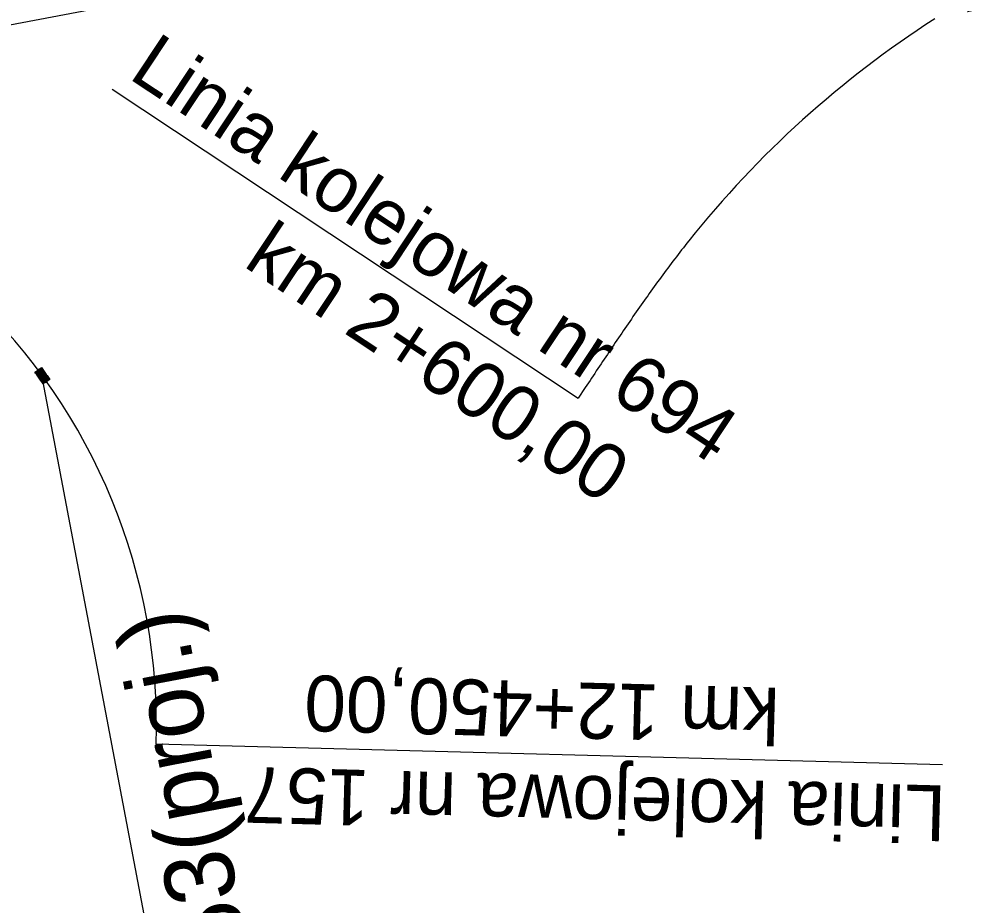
# Model space of a CAD drawing. Extents: x 6540402 to 6566579, y 5525343 to 5532423.
# Drawn here: x 6559226.7 to 6559702.3, y 5528569 to 5529013.3 of the extents above; entities that cross this region are included whole.
import ezdxf

# ---------------------------------------------------------------- set-up
doc = ezdxf.new("R2010")
doc.units = 0
for name, color, linetype in [('TOR_PS_OPIS_T-opisy dodatkowe', 7, 'Continuous'), ('TOR_PS_P-płyty przejazdowe', 7, 'Continuous'), ('TOR_PS_T-tory projektowane', 7, 'Continuous'), ('TOR_RAMKI-ramka+tabelka 2', 7, 'Continuous')]:
    doc.layers.add(name, color=color, linetype=linetype)

msp = doc.modelspace()

# ---------------------------------------------------------------- linework, layer by layer
at = {"layer": 'TOR_PS_OPIS_T-opisy dodatkowe'}
msp.add_line((6559405.62, 5527951.56), (6559238.22, 5528834.7), dxfattribs=at)
at = {"layer": 'TOR_PS_P-płyty przejazdowe'}
for points in [[(6559235.98, 5528836.4), (6559235.02, 5528835.69), (6559234.66, 5528836.17), (6559235.63, 5528836.89)], [(6559236.34, 5528835.91), (6559235.38, 5528835.2), (6559235.02, 5528835.69), (6559235.99, 5528836.4)], [(6559236.11, 5528836.49), (6559237.16, 5528837.26), (6559236.8, 5528837.74), (6559235.75, 5528836.97)], [(6559236.46, 5528836), (6559237.51, 5528836.77), (6559237.16, 5528837.25), (6559236.11, 5528836.48)], [(6559236.82, 5528835.51), (6559237.87, 5528836.28), (6559237.52, 5528836.76), (6559236.47, 5528836)], [(6559238.24, 5528838.06), (6559237.28, 5528837.35), (6559236.92, 5528837.83), (6559237.89, 5528838.54)], [(6559238.6, 5528837.57), (6559237.63, 5528836.86), (6559237.28, 5528837.34), (6559238.25, 5528838.05)], [(6559238.96, 5528837.07), (6559237.99, 5528836.37), (6559237.64, 5528836.85), (6559238.61, 5528837.56)], [(6559239.32, 5528836.58), (6559238.35, 5528835.88), (6559237.99, 5528836.36), (6559238.97, 5528837.07)], [(6559239.67, 5528836.09), (6559238.7, 5528835.39), (6559238.35, 5528835.87), (6559239.32, 5528836.58)], [(6559236.7, 5528835.42), (6559235.73, 5528834.72), (6559235.38, 5528835.2), (6559236.35, 5528835.91)], [(6559237.05, 5528834.94), (6559236.08, 5528834.23), (6559235.73, 5528834.72), (6559236.7, 5528835.42)], [(6559237.41, 5528834.45), (6559236.43, 5528833.75), (6559236.08, 5528834.23), (6559237.05, 5528834.94)], [(6559237.76, 5528833.96), (6559236.78, 5528833.26), (6559236.43, 5528833.75), (6559237.41, 5528834.45)], [(6559238.11, 5528833.47), (6559237.13, 5528832.77), (6559236.78, 5528833.26), (6559237.76, 5528833.96)], [(6559237.17, 5528835.03), (6559238.23, 5528835.79), (6559237.87, 5528836.27), (6559236.82, 5528835.51)], [(6559238.46, 5528832.98), (6559237.48, 5528832.28), (6559237.13, 5528832.77), (6559238.11, 5528833.47)], [(6559237.53, 5528834.54), (6559238.58, 5528835.3), (6559238.23, 5528835.78), (6559237.18, 5528835.02)], [(6559238.81, 5528832.49), (6559237.83, 5528831.79), (6559237.48, 5528832.28), (6559238.46, 5528832.98)], [(6559237.88, 5528834.05), (6559238.93, 5528834.81), (6559238.58, 5528835.29), (6559237.53, 5528834.53)], [(6559239.16, 5528832), (6559238.18, 5528831.3), (6559237.83, 5528831.79), (6559238.81, 5528832.49)], [(6559238.23, 5528833.56), (6559239.29, 5528834.32), (6559238.94, 5528834.8), (6559237.88, 5528834.05)], [(6559239.5, 5528831.5), (6559238.52, 5528830.81), (6559238.18, 5528831.3), (6559239.16, 5528832)], [(6559238.58, 5528833.07), (6559239.64, 5528833.82), (6559239.29, 5528834.31), (6559238.23, 5528833.56)], [(6559238.93, 5528832.58), (6559239.99, 5528833.33), (6559239.64, 5528833.82), (6559238.58, 5528833.06)], [(6559240.03, 5528835.6), (6559239.06, 5528834.89), (6559238.71, 5528835.38), (6559239.68, 5528836.08)], [(6559239.28, 5528832.08), (6559240.34, 5528832.84), (6559239.99, 5528833.32), (6559238.93, 5528832.57)], [(6559240.38, 5528835.1), (6559239.41, 5528834.4), (6559239.06, 5528834.89), (6559240.03, 5528835.59)], [(6559239.63, 5528831.59), (6559240.69, 5528832.34), (6559240.34, 5528832.83), (6559239.28, 5528832.08)], [(6559240.74, 5528834.61), (6559239.76, 5528833.91), (6559239.41, 5528834.4), (6559240.39, 5528835.1)], [(6559239.97, 5528831.1), (6559241.04, 5528831.84), (6559240.69, 5528832.34), (6559239.63, 5528831.59)], [(6559241.09, 5528834.11), (6559240.11, 5528833.42), (6559239.76, 5528833.91), (6559240.74, 5528834.6)], [(6559241.44, 5528833.62), (6559240.46, 5528832.92), (6559240.12, 5528833.41), (6559241.09, 5528834.1)], [(6559241.79, 5528833.12), (6559240.81, 5528832.43), (6559240.46, 5528832.92), (6559241.45, 5528833.61)], [(6559242.14, 5528832.62), (6559241.16, 5528831.93), (6559240.81, 5528832.42), (6559241.8, 5528833.11)], [(6559239.85, 5528831), (6559238.87, 5528830.32), (6559238.53, 5528830.81), (6559239.51, 5528831.5)]]:
    msp.add_lwpolyline(points, close=True, dxfattribs=at)
at = {"layer": 'TOR_PS_T-tory projektowane'}
for p, q in [((6560059.24, 5529168.95), (6558829.07, 5528935.77)), ((6559510.79, 5528828.48), (6559507.28, 5528823.19))]:
    msp.add_line(p, q, dxfattribs=at)
msp.add_lwpolyline([(6559562.65, 5528902), (6559561.76, 5528900.88), (6559560.87, 5528899.76), (6559559.99, 5528898.64), (6559559.11, 5528897.51), (6559558.23, 5528896.39), (6559557.36, 5528895.26), (6559556.49, 5528894.12), (6559555.62, 5528892.99), (6559554.75, 5528891.85), (6559553.89, 5528890.72), (6559553.03, 5528889.57), (6559552.17, 5528888.43), (6559551.32, 5528887.29), (6559550.47, 5528886.14), (6559549.62, 5528884.99), (6559548.77, 5528883.84), (6559547.92, 5528882.69), (6559547.08, 5528881.54), (6559546.24, 5528880.38), (6559545.4, 5528879.23), (6559544.57, 5528878.07), (6559543.73, 5528876.91), (6559542.9, 5528875.75), (6559542.07, 5528874.58), (6559541.24, 5528873.42), (6559540.42, 5528872.25), (6559539.59, 5528871.09), (6559538.77, 5528869.92), (6559537.95, 5528868.75), (6559537.13, 5528867.58), (6559536.32, 5528866.4), (6559535.5, 5528865.23), (6559534.69, 5528864.06), (6559533.88, 5528862.88), (6559533.07, 5528861.7), (6559532.26, 5528860.53), (6559531.45, 5528859.35), (6559530.64, 5528858.17), (6559529.84, 5528856.99), (6559529.04, 5528855.81), (6559528.23, 5528854.63), (6559527.43, 5528853.44), (6559526.63, 5528852.26), (6559525.83, 5528851.07), (6559525.04, 5528849.89), (6559524.24, 5528848.7), (6559523.44, 5528847.52), (6559522.65, 5528846.33), (6559521.85, 5528845.14), (6559521.06, 5528843.96), (6559520.27, 5528842.77), (6559519.47, 5528841.58), (6559518.68, 5528840.39), (6559517.89, 5528839.2), (6559517.1, 5528838.01), (6559516.31, 5528836.82), (6559515.52, 5528835.63), (6559514.73, 5528834.44), (6559513.94, 5528833.25), (6559513.15, 5528832.06), (6559512.36, 5528830.87), (6559511.57, 5528829.68), (6559510.79, 5528828.48)], dxfattribs=at)
for centre, radius, start, end in [((6559961.38, 5528584.02), 510, 122.6719, 141.4279), ((6558998.61, 5528659.2), 297, 358.1728, 94.9458)]:
    msp.add_arc(centre, radius, start, end, dxfattribs=at)
at = {"layer": 'TOR_RAMKI-ramka+tabelka 2'}
for p, q in [((6559273.44, 5528978.11), (6559507.28, 5528823.19)), ((6559689.99, 5528639.32), (6559295.46, 5528649.73))]:
    msp.add_line(p, q, dxfattribs=at)

# ---------------------------------------------------------------- texts
at = {"layer": 'TOR_PS_OPIS_T-opisy dodatkowe'}
for s, p in [('Przebudowa przejazdu kat. A ze zmianą na kat. C ', (6559887.39, 5528185.36)), ('km 12+253(istn.) = km 12+253(proj.)', (6559450.39, 5527973.98))]:
    msp.add_text(s, height=35, rotation=100.7332, dxfattribs=at).set_placement(p)
at = {"layer": 'TOR_RAMKI-ramka+tabelka 2'}
for s, rotation, p in [('Linia kolejowa nr 694', 326.476, (6559281.02, 5528983.94)), ('km 2+600,00', 326.476, (6559338.66, 5528889.65)), ('km 12+450,00', 178.4613, (6559608.54, 5528677.94)), ('Linia kolejowa nr 157', 178.4613, (6559691.94, 5528628.91))]:
    msp.add_text(s, height=28, rotation=rotation, dxfattribs=at).set_placement(p)

doc.saveas('drawing.dxf')
